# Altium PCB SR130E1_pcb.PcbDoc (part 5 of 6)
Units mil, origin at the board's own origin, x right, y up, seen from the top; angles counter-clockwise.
Board outline 5700 x 4800 mil, 6 copper layers (Top Layer, Signal Layer 1, Signal Layer 2, Signal Layer 3, Signal Layer 4, Bottom Layer), stack 61.4 mil thick; 452 components, 288 nets, 1391 pads, 911 vias.
Unrouted connection lines stored in the file: 523.
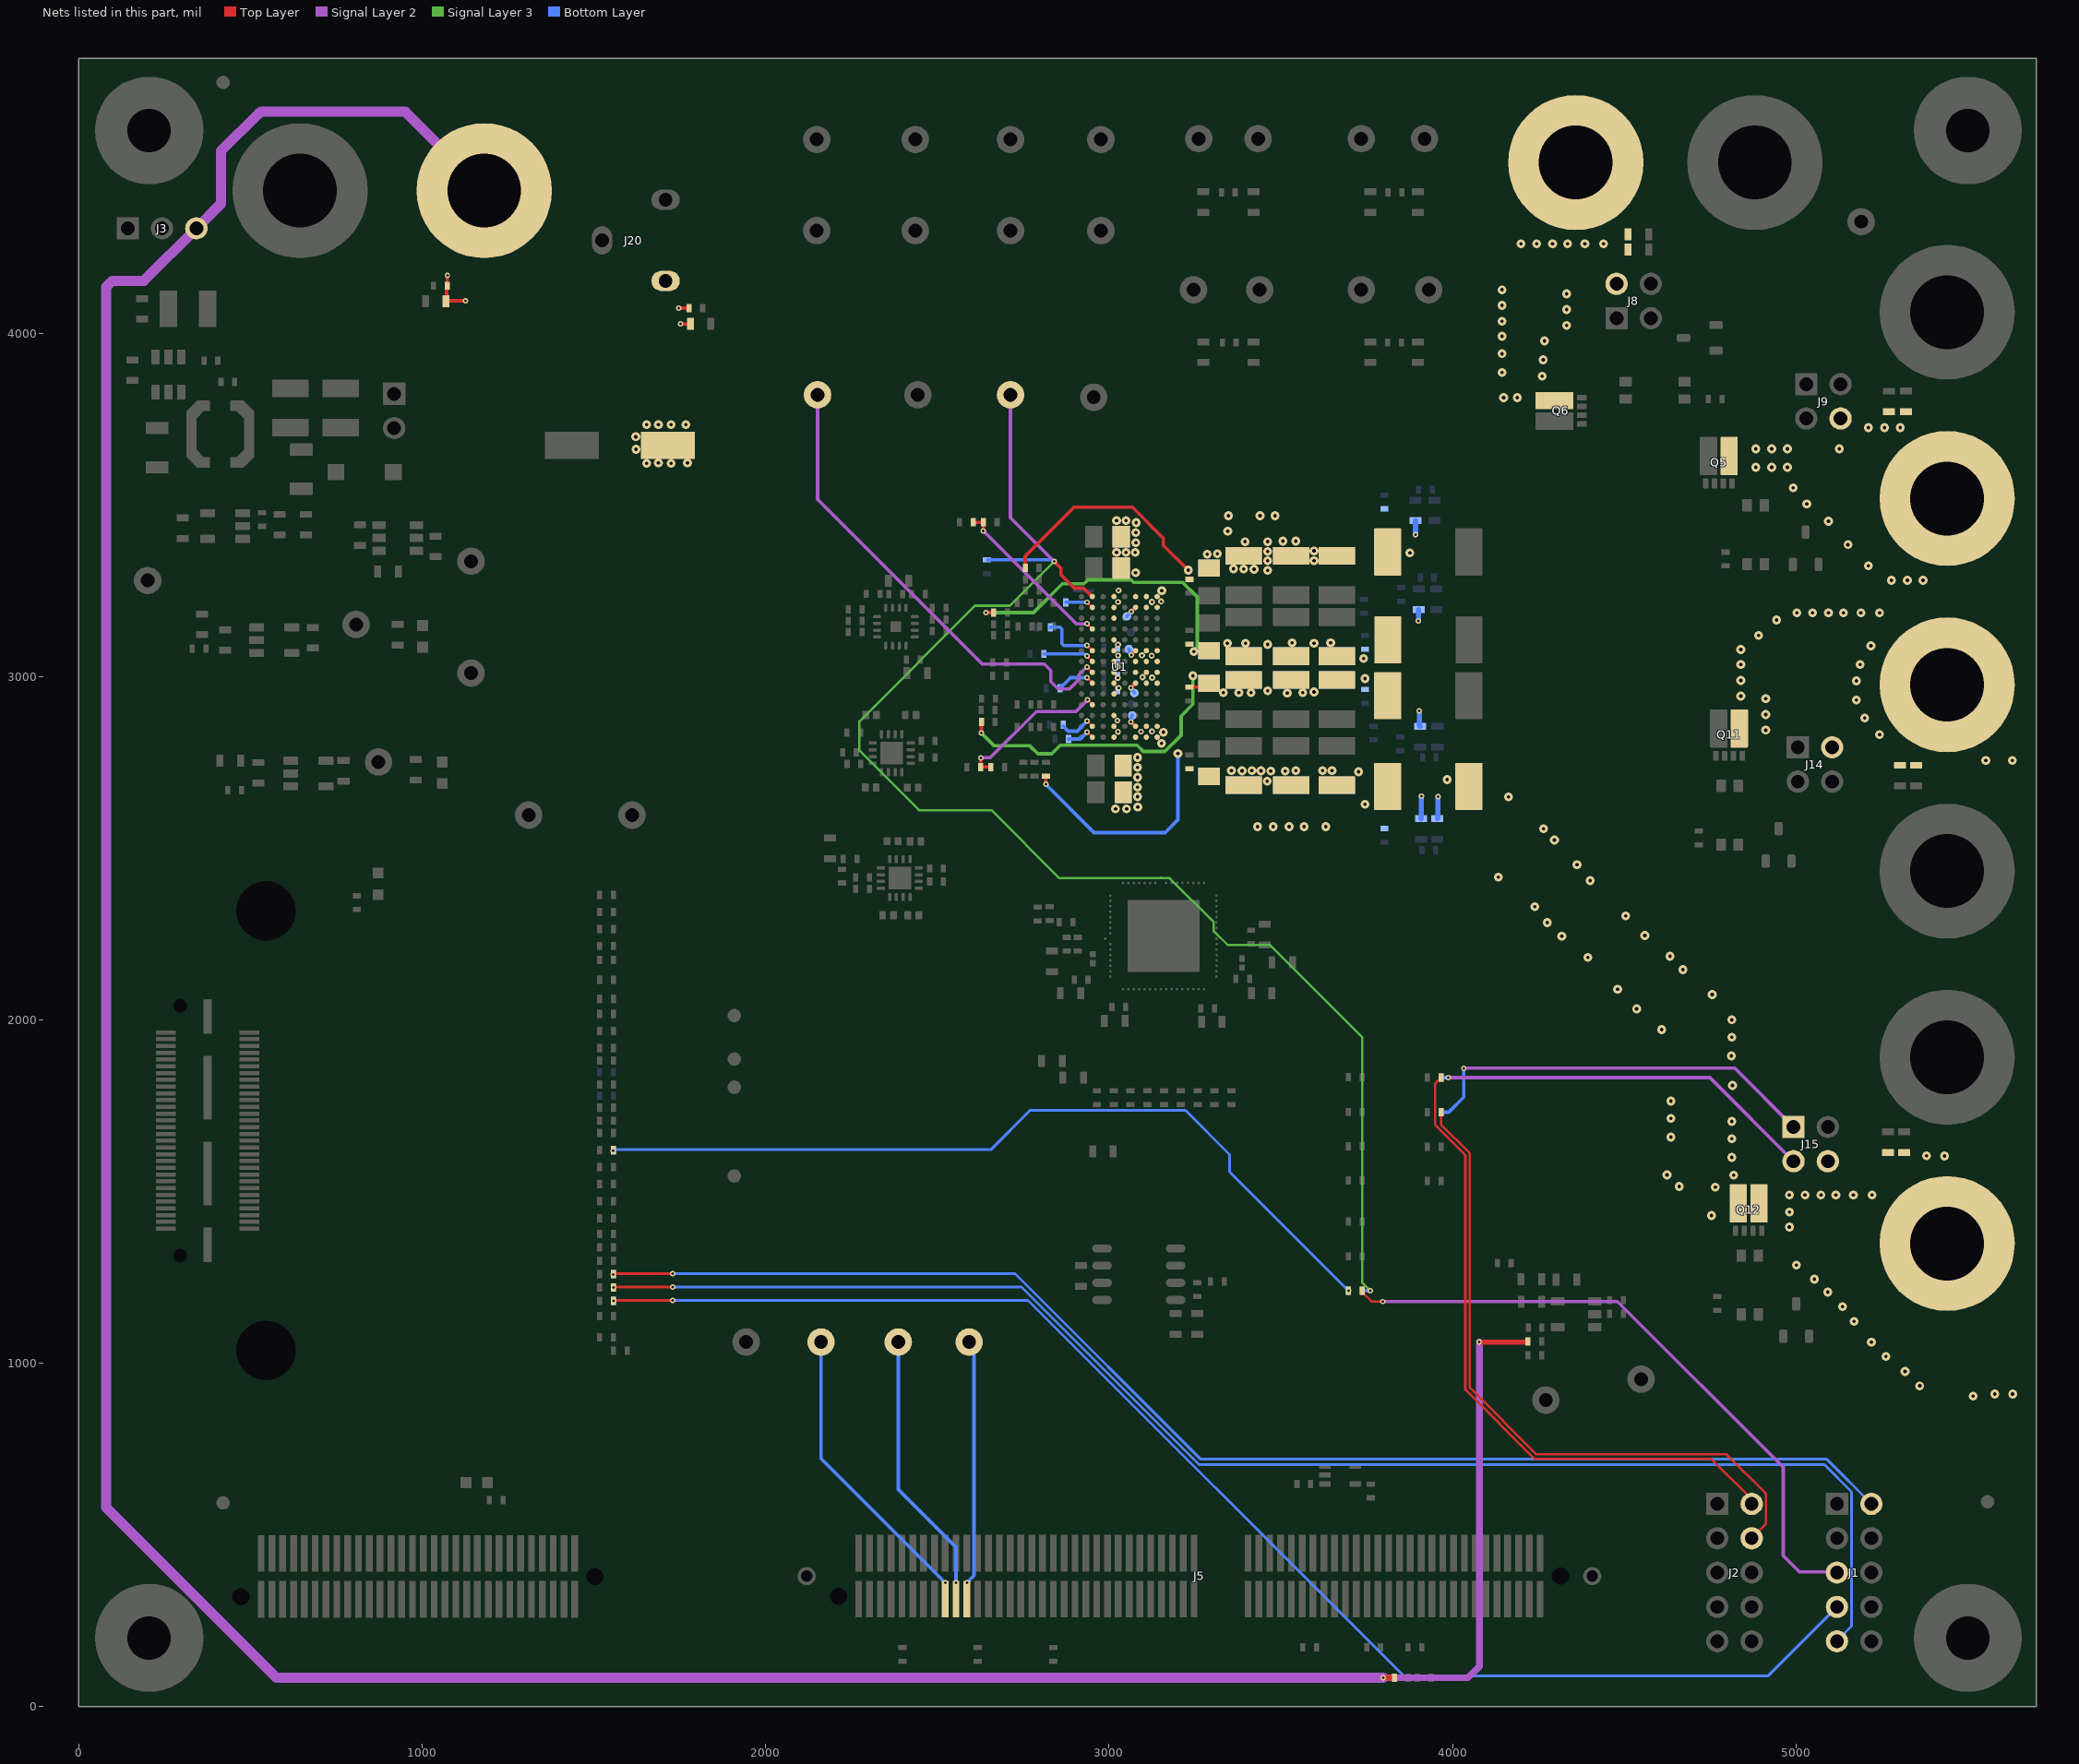
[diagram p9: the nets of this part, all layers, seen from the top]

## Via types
v1: diameter 26, hole 10, Top Layer to Bottom Layer, tented both sides, 435 vias
v2: diameter 16, hole 8, Top Layer to Bottom Layer, tented both sides, 208 vias
v3: diameter 16, hole 8, Top Layer to Bottom Layer, 145 vias
v4: diameter 16, hole 8, Top Layer to Bottom Layer, tented bottom, 46 vias
v5: diameter 19.68, hole 8, Top Layer to Bottom Layer, tented both sides, 35 vias
v6: diameter 17, hole 8, Top Layer to Bottom Layer, 30 vias
v7: diameter 18, hole 8, Top Layer to Bottom Layer, tented both sides, 6 vias
v8: diameter 16, hole 8, Top Layer to Bottom Layer, tented top, 4 vias
v9: diameter 19.68, hole 8, Top Layer to Bottom Layer, 1 vias
v10: diameter 17, hole 8, Top Layer to Bottom Layer, tented both sides, 1 vias

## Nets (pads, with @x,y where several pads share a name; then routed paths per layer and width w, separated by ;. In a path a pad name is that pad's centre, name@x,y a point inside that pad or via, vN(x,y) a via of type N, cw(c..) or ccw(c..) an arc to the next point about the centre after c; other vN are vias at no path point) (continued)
RELAY_IN4: Q12.7 Q12.8 Q12.9 R58.2 R59.2 | length 65.1
  Bottom Layer w15: R59.2@3955.74,2585.92 3957.92,2588.1 3957.92,2649.88 v2(3958.11,2650.07)
  other v1: 4754.08,1430.22 4765.43,1513 4660.38,1514.67 4818.46,1547.81 4624.58,1548.55 4813.41,1599.19 4813.41,1653.73 4636.28,1658.3 4813.41,1704.34 4636.28,1712.84 4636.28,1763.45 4815.36,1808.89 4811.85,1894.86 4813.31,1949.39 4609.31,1971.59 4813.31,2000 4536.27,2031.99 4756.28,2073.51 4480.97,2089.39 4671.31,2146.34 4394.1,2181.56 4633.04,2185.03 4318.43,2243.25 4560,2245.43 4276.13,2283.03 4504.7,2302.83 4239.62,2329.89 4401.24,2405.43 4133.92,2415.36 4362.45,2451.63 4297,2523.49 4265.41,2556.75 4163.04,2649.38 3984.3,2699.72
REMP1: C116.1 C118.1 J8.2 J11.1 Q6.5 Q6.6 Q6.10
  other v1: 4149.29,3811.78 4188.82,3811.78 4261.62,3874.74 4144.71,3885.32 4264.36,3922.12 4144.71,3939.85 4268.09,3977.43 4144.71,3990.46 4332.58,4022.26 4144.71,4033.97 4332.58,4068.75 4144.71,4080.45 4332.58,4114.37 4144.71,4126.08 4199.23,4260 4244.86,4260 4291.35,4260 4334.86,4260 4385.47,4260 4440,4260
REMP2: C117.1 C119.1 J9.4 J13.1 Q5.5 Q5.6 Q5.10
  other v1: 5277.89,3280 5324.37,3280 5370,3280 5211.25,3322.02 5151.55,3383.68 5094.89,3451.91 5031.68,3502.18 4992,3549.34 4882.95,3609.15 4929.43,3609.15 4975.06,3609.15 4882.95,3662.97 4929.43,3662.97 4975.06,3662.97 5126.48,3662.97 5211.25,3724.44 5257.73,3724.44 5303.36,3724.44
REMP3: C120.1 C122.1 J14.2 J18.1 Q11.5 Q11.6 Q11.10
  other v1: 5553,2755.51 5630,2755.51 5243.67,2830.47 4912.23,2843.64 5199.99,2878.63 4912.23,2889.27 5176.11,2931.18 4912.23,2935.76 4839.73,2942.82 5176.11,2987 4839.73,2988.45 5187,3034.45 4839.73,3034.93 4839.73,3078.44 5218.34,3088.99 4891.34,3119.31 4943.73,3164.27 5002.9,3185.51 5048.53,3185.51 5095.01,3185.51 5138.52,3185.51 5189.13,3185.51 5243.67,3185.51
REMP4: C121.1 C123.1 J15.4 J19.1 Q12.5 Q12.6 Q12.10
  other v1: 5515.91,904.52 5579.17,910 5631.12,910 5360.55,934.14 5318.07,975.81 5262.15,1020 5219.67,1061.67 5169.16,1121.63 5136.07,1164.96 5092.98,1206.87 5053.78,1244.78 5001.2,1285.38 4980.94,1396.51 4981.13,1440 4980.94,1490 5026.57,1490 5073.05,1490 5116.56,1490 5167.17,1490 5221.71,1490 5432.77,1603.34 5380.5,1604.39
REMSN4: J15.1 R62.1 | length 1199.6
  Signal Layer 2 w10: v2(4032.85,1859.04) 4821.94,1859.04 J15.1@4992.98,1688
  Bottom Layer w10: R62.1@3966.8,1730.55 3969.02,1730.55 3969.3,1730.83 3988.86,1730.83 4032.85,1774.82 v2(4032.85,1859.04)
REMSP4: J15.3 R60.1 | length 1127.1
  Signal Layer 2 w10: v2(3988.3,1831.59) 4749.39,1831.59 J15.3@4992.98,1588
  Bottom Layer w10: R60.1@3966.8,1831.59 v2(3988.3,1831.59)
RSEN4+_header: J2.2 R61.1 | length 1934.4
  Top Layer w7: R61.1@3966.8,1831.59 3966.8,1827.09 3962.8,1823.09 3958.3,1823.09 3949.8,1814.59 3949.8,1756.38 3949.8,1693.8 4037.45,1606.15 4037.45,923.05 4239.1,721.4 4754.08,721.4 4871.22,604.26 J2.2@4871.22,590.24
RSEN4-_header: J2.4 R63.1 | length 1974.3
  Top Layer w7: R63.1@3966.8,1730.55 3966.8,1695.18 4050.45,1611.54 4050.45,928.44 4244.48,734.4 4798.53,734.4 4913.2,619.73 4913.2,532.22 J2.4@4871.22,490.24
RT1: R2.2 U1.B8 | length 150
  Top Layer w7: v2(2935.75,3059.37) 2935.75,3059.28 2950.58,3044.46 U1.B8@2951.42,3044.46
  Bottom Layer w10: R2.2@2810.24,3065.69 2927.81,3065.69 2934.13,3059.37 v2(2935.75,3059.37)
RT2: R8.2 U1.B1 | length 83.6
  Top Layer w7: v2(2935.87,2838.02) 2936.17,2838.02 2950.2,2823.98 U1.B1@2951.42,2823.98
  Bottom Layer w10: R8.2@2882.26,2817.98 2916.32,2817.98 2935.87,2837.53 v2(2935.87,2838.02)
SS1: C1.1 U1.B13 | length 85
  Top Layer w7: v2(2936.09,3216.18) 2936.09,3215.9 2951.91,3200.07 U1.B13@2951.91,3199.79
  Bottom Layer w10: C1.1@2874.14,3215.96 2874.25,3216.07 2935.98,3216.07 v2(2936.09,3216.18)
SS2: C4.1 U1.B9 | length 174.8
  Top Layer w7: v2(2935.99,3090.06) 2936.19,3090.06 2950.58,3075.67 U1.B9@2951.42,3075.67
  Bottom Layer w10: C4.1@2829.57,3143.15 2830.12,3143.7 2856.81,3143.7 2862.67,3137.84 2862.67,3095.91 2868.52,3090.06 v2(2935.99,3090.06)
SS3: C9.1 U1.B6 | length 115.9
  Top Layer w7: v2(2935.76,2996.74) 2951.03,2981.46 U1.B6@2951.42,2981.46
  Bottom Layer w10: C9.1@2857.31,2965.67 2857.31,2970.17 2859.81,2972.67 2864.31,2972.67 2888.38,2996.74 v2(2935.76,2996.74)
SS4: C17.1 U1.B2 | length 109.4
  Top Layer w7: v2@2936.22,2870.96 2951.42,2855.76 U1.B2@2951.42,2855.48
  Bottom Layer w10: C17.1@2866.66,2855.19 2880.87,2840.98 2907.54,2840.98 v2(2936.45,2869.89)
SW1: pad.2@3052.27,3175.01 U1.F13 | length 31.1
  Top Layer w10: v8(3064.62,3189) 3064.62,3190.62 U1.F13@3070.95,3196.95 ; U1.F13@3076.29,3200.07 U1.F13@3077.32,3201.1
  Bottom Layer w10: pad.2@3052.27,3175.01 3052.27,3175.83 3064.62,3188.18 v8(3064.62,3189)
SW2: pad.2@3057.91,3079.86 U1.F9 | length 38.5
  Top Layer w10: v8@3064.84,3062.4 3077.32,3074.88 U1.F9@3077.32,3075.12
  Bottom Layer w10: pad.2@3057.91,3079.86 3059.82,3077.95 3059.82,3068.8 3064.84,3063.78 v8(3064.84,3062.16)
SW3: pad.2@3073.81,2951.75 U1.F6 | length 38.8
  Top Layer w10: v8@3063.65,2967.01 U1.F6@3077.32,2980.63
  Bottom Layer w10: v8(3063.61,2967.01) 3064.76,2965.86 3064.76,2963.5 3073.81,2954.45 pad.2@3073.81,2951.75
SW4: pad.2@3067.43,2886.51 U1.F2 | length 39.2
  Top Layer w10: v8(3064.07,2867.42) 3064.31,2867.42 3076.86,2854.87 3076.86,2854.64 U1.F2@3077.32,2854.64
  Bottom Layer w10: v8(3064.07,2867.42) 3064.07,2869.05 3065.52,2870.49 3065.52,2884.6 pad.2@3067.43,2886.51
SYNC_DCDC: R66.2 R67.2 R138.2 R153.1 | length 2434.8
  Top Layer w8: R153.1@1557.16,1620.6 R153.1@1558.3,1621.75
  Bottom Layer w8: R138.2@1558.3,1621.75 1730,1621.75 2655.9,1621.75 2770.24,1736.08 3222.6,1736.08 3351.16,1607.52 3351.16,1557.29 v2(3697.27,1211.18)
  other v3: 1556.18,1618.85
SYNC_DCDC_header: J1.5 R67.1 | length 1875.3
  Top Layer w7: R67.1@3737.27,1211.18 3737.27,1206.68 3764.39,1179.56 v3(3797.52,1179.56)
  Signal Layer 2 w10: v3(3797.52,1179.56) 4480.44,1179.56 4962.91,697.09 4962.91,439.39 5010.17,392.13 5059.17,392.13 J1.5@5119.67,392.13
SYNC_EX_2: J1.7 R116.1 R171.2 | length 4098.7
  Top Layer w8: R171.2@1557.16,1181.96 1558.3,1183.11 v3(1730,1183.11)
  Bottom Layer w8: v3(1730,1183.11) 2764.31,1183.11 3857.41,90 4919.43,90 J1.7@5119.67,290.24
  other v3: 1557.33,1182.13
SYNC_EX_3: J1.9 R117.1 R172.2 | length 4303.6
  Top Layer w8: R172.2@1557.16,1220.76 1558.3,1221.91 v3(1730,1221.91)
  Bottom Layer w8: v3(1730,1221.91) 2745.3,1221.91 3262.53,704.68 5083.19,704.68 5162.15,625.72 5162.15,234.61 J1.9@5119.67,192.13
  other v3: 1557.43,1220.94
SYNC_EX_4: J1.2 R118.1 R173.2 | length 3940.7
  Top Layer w8: R173.2@1557.16,1259.57 1558.3,1260.71 v3(1730,1260.71)
  Bottom Layer w8: v3(1730,1260.71) 2726.3,1260.71 3265.61,721.4 5088.5,721.4 J1.2@5219.67,590.24
  other v3: 1556.18,1258.6
SYNC_OUT: TP7.1 U1.B7 | length 1393.3
  Top Layer w7: v2(2935.57,3028.02) 2950.63,3012.96 U1.B7@2951.42,3012.96
  Signal Layer 2 w10: TP7.1@2151.38,3820.18 2151.38,3515.56 2630.99,3035.95 2811.64,3035.95 2830.25,3017.35 2830.25,2985.27 2852.09,2963.42 2884.63,2963.42 2889.21,2968 2889.41,2968 2912.67,2991.26 2912.67,3005.11 v2(2935.57,3028.02)
SYNC_powerSch: R13.2 R66.1 TP3.1 U1.B14 | length 4342.8
  Top Layer w10: v2(2840.07,3335.09) 2859.71,3315.44 2859.71,3296.55 2898.9,3257.35 2925.85,3257.35 U1.B14@2951.91,3231.29
  Signal Layer 2 w10: TP3.1@2713.15,3820.18 2713.15,3462 v2(2840.07,3335.09)
  Signal Layer 3 w7: v2(2840.07,3335.09) 2711.13,3206.15 2609.84,3206.15 2273.24,2869.55 2273.24,2784.11 2446.67,2610.67 2657.39,2610.67 2855.29,2412.78 3176.93,2412.78 3305.25,2284.46 3305.25,2257.93 3345.05,2218.14 3468.59,2218.14 3737.27,1949.46 3737.27,1234.82 v2(3760.9,1211.18)
  Bottom Layer w10: R13.2@2644.92,3339.8 2833.73,3339.8 2838.44,3335.09 v2(2840.07,3335.09) ; R66.1@3737.27,1211.18 v2(3760.9,1211.18)
TEST1: J5.100 TP35.1 | length 763.2
  Top Layer w10: J5.100@2586.1,313.07 v3(2586.1,360.5)
  Bottom Layer w10: v3(2586.1,360.5) 2607.1,381.5 2607.1,1020.81 2606.23,1021.68 2606.23,1048.27 TP35.1@2592.83,1061.66
TEST2: J5.102 TP36.1 | length 818.3
  Top Layer w10: J5.102@2554.6,313.07 v3(2554.6,360.5)
  Bottom Layer w10: TP36.1@2386.33,1061.66 2386.33,632.2 2554.6,463.93 v3(2554.6,360.5)
TEST3: J5.104 TP37.1 | length 901.3
  Top Layer w10: J5.104@2523.11,313.07 v3(2523.11,360.5)
  Bottom Layer w10: TP37.1@2159.54,1059.56 TP37.1@2161.65,1061.66 2161.65,721.96 v3(2523.11,360.5)
V_HV: C6.1 C7.1 C8.1 C10.1 C13.1 C14.1 C15.1 C16.1 C18.1 C19.1 C20.1 C21.1 C22.1 C23.1 C24.1 C124.1 C125.1 J3.3 J20.1 J21.1 R103.2 R146.2 U1.D1 U1.D2 U1.D3 U1.D5 U1.D6 U1.D7 U1.D8 U1.D9 U1.D10 U1.D12 U1.D13 U1.D14 | length 10578.4
  Top Layer w10: C6.1@1069.77,4092.17 C6.1@1071.59,4093.98 ; v3(1073.4,4167.68) C7.1@1073.4,4137.68 1071.59,4135.87 C6.1@1071.59,4093.98 ; v3(1126.37,4094.38) 1071.98,4094.38 C6.1@1071.59,4093.98 ; v3(1747.33,4072.49) C125.1@1777.01,4072.49 ; v3(1751.92,4026.56) C124.1@1780.79,4026.56
  Top Layer w15: v2(3798.03,84.04) 3830.93,84.04 R146.2@3830.93,83.63 ; v2(4078.15,1061.72) R103.2@4218.44,1061.72
  Signal Layer 2 w20: v2(3798.03,84.04) 3830.52,84.04 ; 3830.93,83.63 3830.52,84.04 ; v2(4078.15,1061.72) 4078.15,117.43 4044.76,84.04 3830.52,84.04
  Signal Layer 2 w30: J21.1@1180.94,4414.96 950.91,4645 531.22,4645 526.22,4640 524.5,4640 414.61,4530.11 414.61,4376.82 J3.3@342.74,4304.95 189.25,4151.46 97.57,4151.46 80,4133.89 80,579.37 575.33,84.04 v2(3798.03,84.04)
  other v1: 3019.03,2614.21 3051.25,2614.21 3083.92,2619.37 3083.21,2650.07 3083.21,2677.44 3083.21,2706.14 3083.21,2735.22 3083.21,2764.09 3077.28,3302.44 3022.07,3361.43 3049.6,3361.43 3076.29,3361.43 3078.13,3389.64 3078.13,3418.9 3079.1,3447.78 3022.07,3454.31 3049.6,3454.31 1653.7,3620.51 1725.26,3620.87 1688.06,3621.9 1772.63,3621.9 1622.61,3661.56 1622.33,3698.04 1653.7,3733.2 1688.06,3733.2 1768.05,3733.2 1725.26,3733.71
  other v6: 3025.99,2839.09 3024.64,2871.46 3028.11,2966.32 3025.6,2995.85 3025.88,3028.28 3026.42,3061 3026.42,3092.57 3026.42,3216.85 3027.95,3250.61
VCC1: R16.2 R17.2 U1.B11 | length 491
  Top Layer w7: v2(2936.09,3153.17) 2951.91,3137.34 U1.B11@2951.91,3136.8
  Top Layer w10: R17.2@2605.04,3448.85 R16.2@2634.09,3448.85 v2(2634.09,3424)
  Signal Layer 2 w10: v2(2634.09,3424) 2904.92,3153.17 v2(2936.09,3153.17)
VCC2: R20.2 R21.2 U1.B4 | length 459.5
  Top Layer w7: v2@2935.98,2933.95 U1.B4@2951.42,2918.51
  Top Layer w10: v2(2626.53,2763.36) 2626.35,2763.18 2626.35,2736.6 R20.2@2626.16,2736.42 R21.2@2655.74,2736.42
  Signal Layer 2 w10: v2(2626.53,2763.36) 2654.23,2763.36 2788.78,2897.9 2903.67,2897.9 v2(2937.7,2931.93)
VOUT1: C26.1 C31.1 C35.1 C39.1 C43.1 C47.1 C51.1 C56.1 C60.1 R24.1 R26.2 R31.2 R35.1 U1.F14 U1.G13 U1.G14 U1.H13 U1.H14 | length 696.6
  Top Layer w10: R26.2@2756.23,3316.25 2756.23,3350.56 2898.43,3492.76 3068.06,3492.76 3158.29,3402.53 3158.29,3381.67 v1(3230.6,3309.36)
  Bottom Layer w15: v2(3892.6,3412.62) R31.2@3892.6,3453.49
  other v1: 3153.62,3250.02 3461.78,3309 3422.52,3312.09 3391.78,3313.17 3362.35,3313.58 3462.12,3336.97 3597.07,3337.38 3285.57,3355.56 3315.67,3356.88 3876.1,3359.73 3462.12,3364.08 3597.07,3365.67 3396.35,3392.57 3462.12,3392.57 3506.05,3393.93 3543.79,3393.93 3345.52,3423.35 3347.62,3468.26 3439.73,3468.26 3483.24,3468.26
  other v7: 3124.98,3216.74 3151.96,3218.56
VOUT2: C27.1 C32.1 C36.1 C40.1 C44.1 C48.1 C52.1 C57.1 C61.1 R25.1 R29.2 R37.2 R40.1 U1.F8 U1.G8 U1.G9 U1.H8 U1.H9 | length 899.2
  Top Layer w10: v2(2641.64,3185.81) R29.2@2664.37,3185.81
  Signal Layer 2 w10: v1(3597.07,3096.49) v1@3601.4,3096.49
  Signal Layer 3 w10: v2(2641.64,3185.81) 2780.08,3185.81 2863.97,3269.7 2927.22,3269.7 2938.87,3281.35 3064.42,3281.35 3071.76,3274.02 3214.39,3274.02 3256.85,3231.55 3256.85,3086.67 3246.8,3076.62 v1(3246.8,3072.29)
  Bottom Layer w10: R37.2@3901.05,3194.18 R37.2@3901.58,3194.71
  Bottom Layer w15: v2(3901.05,3161.58) R37.2@3901.05,3194.18
  other v1: 3741.19,3051.96 3462.12,3093.06 3344.65,3096.49 3397.34,3096.72 3532.8,3098 3645.32,3098
  other v7: 3095.77,3061.27
  other v10: 3124.23,3060.33
VOUT3: C28.1 C33.1 C37.1 C41.1 C45.1 C49.1 C53.1 C58.1 C62.1 R22.1 R39.2 R54.2 R55.1 U1.F7 U1.G6 U1.G7 U1.H6 U1.H7 | length 971.7
  Top Layer w10: v2(2628.47,2835.26) R39.2@2628.47,2867.73 ; C28.1@3234.42,2968.8 3281.14,2968.8 C37.1@3291.67,2979.34
  Signal Layer 3 w10: v2(2628.47,2835.26) 2665.71,2798.01 2769.45,2798.01 2792.62,2774.84 2833.45,2774.84 2858.41,2799.8 3081.44,2799.8 3099.97,2781.27 3162.57,2781.27 3209.86,2828.56 3209.86,2884.57 3244.54,2919.25 v1(3244.54,3002)
  Bottom Layer w15: v2(3903.67,2899.34) 3903.67,2857.22 3906.17,2854.72 R54.2@3906.27,2854.72
  other v1: 3519.08,2951.75 3333.17,2952.69 3378.04,2952.69 3413.73,2952.69 3563.94,2952.69 3597.07,2954.86 3462.12,2957.97 3745.25,2993.63
  other v7: 3125.61,2996.62 3097.82,2997.59
VOUT4: C29.1 C34.1 C38.1 C42.1 C46.1 C50.1 C54.1 C59.1 C63.1 R23.1 R32.2 R56.2 R58.1 U1.F1 U1.G1 U1.G2 U1.H1 U1.H2 | length 741.7
  Top Layer w10: v2(2815.92,2685.82) R32.2@2815.92,2710.14
  Bottom Layer w10: v2(2815.92,2685.82) 2956.4,2545.34 3163.54,2545.34 3200.85,2582.65 v1(3200.85,2775.28)
  Bottom Layer w15: R56.2@3908.18,2585.92 3909.51,2587.25 v2(3909.51,2651.53)
  other v1: 3432.43,2562.67 3478.06,2562.67 3524.55,2562.67 3568.06,2562.67 3630.86,2562.67 3745.54,2627.61 3460.8,2694.83 3726.67,2722.68 3470.94,2724.31 3387.2,2725.09 3442.28,2725.09 3513.3,2724.68 3356.66,2725.66 3415.85,2725.66 3543.68,2725.66 3621.42,2726.07 3649.51,2725.66 3152.63,2805.27 3158.06,2837.74
  other v2: 3093.15,2839.37
  other v7: 3124.98,2839.73
pads on no net: FID1.1 FID2.1 FID3.1 H1.0 H2. H3.1 H4. H5.0 H6.1 H7.0 H8.1 H10.0 H11.1 J5.1 J5.2 J5.3 J5.4 J5.5 J5.6 J5.8 J5.9 J5.11 J5.12 J5.14 J5.15 J5.17 J5.18 J5.20 J5.21 J5.23 J5.24 J5.25 J5.26 J5.27 J5.31 J5.32 J5.33 J5.34 J5.36 J5.37 J5.39 J5.40 J5.41 J5.42 J5.43 J5.44 J5.45 J5.51 J5.52 J5.55 J5.56 J5.59 J5.60 J5.63 J5.64 J5.66 J5.76 J5.77 J5.78 J5.80 J5.82 J5.86 J5.88 J5.90 J5.92 J5.94 J5.106 J5.107 J5.108 J5.109 J5.110 J5.113 J5.114 J5.115 J5.116 J5.117 J5.118 J5.119 J5.120 J5.181 J5.182 J5.185 J5.186 J6.61 J6.62 J6.121 J6.122 J6.123 J6.124 J6.125 J6.126 J6.127 J6.128 J6.129 J6.130 J6.131 J6.132 J6.133 J6.134 J6.136 J6.137 J6.138 J6.139 J6.140 J6.141 J6.142 J6.143 J6.144 J6.145 J6.146 J6.147 J6.148 J6.149 J6.150 J6.151 J6.152 J6.153 J6.154 J6.155 J6.156 J6.159 J6.160 J6.161 J6.162 J6.163 J6.164 J6.165 J6.166 J6.167 J6.168 J6.169 J6.170 J6.171 J6.172 J6.173 J6.174 J6.175 J6.176 J6.177 J6.178 J7.1 J7.2 J7.4 J7.5 J7.9 J7.11 J7.13 J7.15 J7.17 J7.19 J7.21 J7.23 J7.25 J7.34 J7.36 J7.39 J7.41 J7.43 J7.45 J7.47 J7.49 J7.51 J7.53 J7.55 J7.56 J7.57 J7.58 J7.59 J7.MH1 J7.MH2 LBL1.0 SH-J1.0 SH-J2.0 SH-J3.0 SH-J4.0 SH-J5.0 SH-J6.0 SH-J7.0 SH-J8.0 SH-J9.0 SH-J10.0 U1.A1 U1.A14 U2.1 U2.3 U2.7 U2.8 U3.41 U3.42 U3.43 U3.44 U3.45 U3.46 U6.4 U9.4 U10.4 U11.1 U11.5 U12.6 U12.7 U13.6 U13.7

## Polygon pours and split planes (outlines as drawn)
PGND on Signal Layer 1 "SIGNAL_LAYER_1_PGND_P137" (solid, remove dead copper, pour order 137): 0,4800 5700,4800 5700,0 0,0
V_HV on Signal Layer 1 "SIGNAL_LAYER_1_V_HV_P136" (solid, remove dead copper, pour order 136): 932.05,4800 932.05,4261.61 1278.01,3915.65 1408.27,3915.65 1582.83,3741.09 1582.83,2905.06 1907.54,2580.35 3122.11,2580.35 3122.11,3503.11 3035.22,3590 2236.5,3590 1797.01,4029.49 1797.01,4145.06 1725.22,4216.85 1496.41,4216.85 1440,4273.26 1440,4800
RELAY_IN3 on Bottom Layer "BOTTOM_LAYER_RELAY_IN3_P149" (solid, remove dead copper, pour order 149): 3934.65,2993.63 3934.65,2892 3955.33,2871.32 4243.84,2871.32 4349.45,2765.71 4782.36,2765.71 4799.78,2783.13 4799.78,2963.45 4744.11,3019.11 3960.13,3019.11
REMP3 on Bottom Layer "BOTTOM_LAYER_REMP3_P133" (solid, remove dead copper, pour order 133): 5700,3232.6 5697.79,3232.6 4940.98,3232.6 4804.32,3095.94 4804.32,2795.65 4815.36,2784.6 4899.01,2784.6 4958.91,2844.5 4959.76,2843.64 5048.03,2843.64 5060.08,2831.6 5060.08,2746.36 5077.99,2728.45 5700,2728.45
VOUT1 on Bottom Layer "BOTTOM_LAYER_VOUT1_P106" (solid, remove dead copper, pour order 106): 3388.73,3501.03 3322.03,3501.03 3064.29,3243.29 3064.29,3226.35 3099.29,3191.35 3164.66,3191.35 3219.2,3269.34 3471.84,3269.34 3500.18,3297.67 3747.84,3297.67 3755.84,3289.67 3882.81,3289.67 3919.29,3326.15 3919.29,3459.66 3877.92,3501.03
REMP4 on Bottom Layer "BOTTOM_LAYER_REMP4_P141" (solid, remove dead copper, pour order 141): 4857.55,1419.69 4874.11,1403.13 4920.03,1403.13 4938.74,1384.43 4939.64,1290.91 5360.55,870 5700,870 5700,1638 5060.99,1638 5042.98,1619.98 5042.98,1588 4992.98,1538 4884.49,1538 4857.26,1510.77
RELAY_IN4 on Bottom Layer "BOTTOM_LAYER_RELAY_IN4_P152" (solid, remove dead copper, pour order 152): 3990.56,2750.21 3990.56,2746.2 3935.46,2691.11 3935.46,2574.97 3988.93,2521.5 4600,1910.44 4600,1541.18 4737.46,1403.72 4850.71,1403.72 4857.37,1410.37 4857.37,1999.13 4106.29,2750.21
VOUT4 on Bottom Layer "BOTTOM_LAYER_VOUT4_P134" (solid, remove dead copper, pour order 134): 3070.58,2813.49 3143.86,2740.21 3143.87,2697.97 3316.78,2525.05 3892.47,2525.05 3933.01,2565.59 3933.01,2681.95 3866.12,2748.83 3271.68,2748.83 3153.74,2866.78 3088.24,2866.78 3070.58,2849.11
VOUT3 on Bottom Layer "BOTTOM_LAYER_VOUT3_P131" (solid, remove dead copper, pour order 131): 3087.21,3022.02 3087.16,3021.96 3072.47,3021.96 3072.47,3021.94 3062.47,3011.93 3062.47,3006.47 3079.57,2989.37 3079.57,2974.01 3093.61,2959.97 3215.7,2959.59 3238.39,2936.9 3715.35,2936.9 3780.94,2871.32 3911.64,2871.32 3930.51,2890.19 3930.51,2982.92 3891.41,3022.02 3226.23,3022.02
VOUT2 on Bottom Layer "BOTTOM_LAYER_VOUT2_P109" (solid, remove dead copper, pour order 109): 3196.76,3087.69 3104.01,3087.69 3072.76,3056.44 3072.76,3042.65 3087.62,3027.78 3891.38,3027.78 3927.01,3063.41 3927.01,3175.21 3922.21,3180.01 3845.05,3180.01 3768.57,3180.01 3759.2,3170.64 3759.2,3113.62 3740.49,3110.91 3220.08,3110.91 3216.66,3107.49 3216.69,3107.62
RELAY_IN2 on Bottom Layer "BOTTOM_LAYER_RELAY_IN2_P143" (solid, remove dead copper, pour order 143): 3931.69,3059.79 3931.69,3174.68 3947.57,3185.39 4179.78,3185.64 4712.33,3718.19 4766.21,3718.19 4777.17,3707.23 4777.17,3593.27 4767.67,3583.77 4733.34,3583.77 4719.46,3569.9 4719.46,3157.37 4587.04,3024.94 3966.54,3024.94
REMP2 on Bottom Layer "BOTTOM_LAYER_REMP2_P130" (solid, remove dead copper, pour order 130): 4780.31,3708.9 4774.81,3703.4 4774.81,3586.34 4782.45,3578.7 4910.5,3578.7 5247.18,3242.02 5700,3242.02 5700,3801.11 5105.27,3801.11 5084.11,3779.95 5071.63,3708.9
REMP1 on Bottom Layer "BOTTOM_LAYER_REMP1_P108" (solid, remove dead copper, pour order 108): 4140.41,3780.55 4144.71,3776.24 4355.06,3776.5 4359.11,3780.55 4359.11,3999.25 4461.54,4101.69 4502.42,4101.69 4527.79,4127.06 4527.79,4282.24 4610,4364.45 4610,4800 4107.85,4800 4107.85,3813.11 4141.74,3779.21
RELAY_IN1 on Bottom Layer "BOTTOM_LAYER_RELAY_IN1_P142" (solid, remove dead copper, pour order 142): 3926.22,3342.88 3926.22,3464.36 3945.33,3483.47 4003.46,3541.6 4003.46,3676.69 4100.09,3773.32 4352.63,3773.32 4358.93,3767.02 4358.93,3558.93 4089.67,3289.67 3979.42,3289.67
V_HV on Bottom Layer "BOTTOM_LAYER_V_HV_P102" (solid, remove dead copper, pour order 102): 1582.83,3514.65 1622.61,3474.88 2100.09,3474.88 2151.38,3526.16 2151.38,3668.62 1797.01,4022.99 1797.01,4159.76 1782.3,4159.76 1725.22,4216.85 1496.41,4216.85 1440,4273.26 1440,4800 932.05,4800 932.05,4261.61 1278.01,3915.65 1408.27,3915.65 1582.83,3741.09
PGND on Bottom Layer "BOTTOM_LAYER_PGND_P158" (solid, remove dead copper, pour order 158): 5353.54,870 5120,1103.54 4568.63,1654.91 4568.63,1917.06 3962.2,2523.49 3962.2,2548.24 1929.46,2548.24 1582.83,2894.87 1582.83,3209.53 1158.47,3633.9 119.55,3633.9 0,3753.45 0,4800 5700,4800 5700,870
AGND on Bottom Layer "BOTTOM_LAYER_AGND_P163" (solid, remove dead copper, pour order 163): 0,4800 5700,4800 5700,0 0,0
AGND on Bottom Layer "BOTTOM_LAYER_AGND_P105" (solid, remove dead copper, pour order 105): 2919.69,3336.86 2919.69,2794.8 2618.84,2794.8 2609.49,3336.86
V_HV on Bottom Layer "BOTTOM_LAYER_V_HV_P103" (solid, remove dead copper, pour order 103): 3125.53,3507.49 3003.88,3507.49 3003.88,2553.93 3161.84,2553.93 3161.84,2713.86 3083.16,2792.55 3083.16,3275.38 3125.53,3317.76
RELAY_IN3 on Top Layer "TOP_LAYER_RELAY_IN3_P165" (solid, remove dead copper, pour order 165): 3934.65,2993.63 3934.65,2892 3955.33,2871.32 4243.84,2871.32 4349.45,2765.71 4782.36,2765.71 4799.78,2783.13 4799.78,2963.45 4744.11,3019.11 3960.13,3019.11
REMP3 on Top Layer "TOP_LAYER_REMP3_P157" (solid, remove dead copper, pour order 157): 5700,3232.6 5697.79,3232.6 4940.98,3232.6 4804.32,3095.94 4804.32,2795.65 4815.36,2784.6 4899.01,2784.6 4958.91,2844.5 4959.76,2843.64 5048.03,2843.64 5060.08,2831.6 5060.08,2746.36 5077.99,2728.45 5700,2728.45
RELAY_IN4 on Top Layer "TOP_LAYER_RELAY_IN4_P166" (solid, remove dead copper, pour order 166): 3990.56,2750.21 3990.56,2746.2 3935.46,2691.11 3935.46,2574.97 3988.93,2521.5 4600,1910.44 4600,1541.18 4737.46,1403.72 4850.71,1403.72 4857.37,1410.37 4857.37,1999.13 4106.29,2750.21
RELAY_IN2 on Top Layer "TOP_LAYER_RELAY_IN2_P164" (solid, remove dead copper, pour order 164): 3931.69,3059.79 3931.69,3174.68 3947.57,3185.39 4179.78,3185.64 4712.33,3718.19 4766.21,3718.19 4777.17,3707.23 4777.17,3593.27 4767.67,3583.77 4733.34,3583.77 4719.46,3569.9 4719.46,3157.37 4587.04,3024.94 3966.54,3024.94
RELAY_IN1 on Top Layer "TOP_LAYER_RELAY_IN1_P161" (solid, remove dead copper, pour order 161): 3926.22,3342.88 3926.22,3464.36 3945.33,3483.47 4003.46,3541.6 4003.46,3676.69 4100.09,3773.32 4352.63,3773.32 4358.93,3767.02 4358.93,3558.93 4089.67,3289.67 3979.42,3289.67
REMP4 on Top Layer "TOP_LAYER_REMP4_P160" (solid, remove dead copper, pour order 160): 4857.55,1419.69 4874.11,1403.13 4920.03,1403.13 4938.74,1384.43 4939.64,1290.91 5360.55,870 5700,870 5700,1638 5060.99,1638 5042.98,1619.98 5042.98,1588 4992.98,1538 4884.49,1538 4857.26,1510.77
VOUT4 on Top Layer "TOP_LAYER_VOUT4_P159" (solid, remove dead copper, pour order 159): 3070.58,2813.49 3143.86,2740.21 3143.87,2697.97 3316.78,2525.05 3892.47,2525.05 3933.01,2565.59 3933.01,2681.95 3866.12,2748.83 3271.68,2748.83 3153.74,2866.78 3088.24,2866.78 3070.58,2849.11
VOUT3 on Top Layer "TOP_LAYER_VOUT3_P156" (solid, remove dead copper, pour order 156): 3087.21,3022.02 3087.16,3021.96 3072.47,3021.96 3072.47,3021.94 3062.47,3011.93 3062.47,3006.47 3079.57,2989.37 3079.57,2974.01 3093.61,2959.97 3215.7,2959.59 3238.39,2936.9 3715.35,2936.9 3780.94,2871.32 3911.64,2871.32 3930.51,2890.19 3930.51,2982.92 3891.41,3022.02 3226.23,3022.02
REMP2 on Top Layer "TOP_LAYER_REMP2_P155" (solid, remove dead copper, pour order 155): 4780.31,3708.9 4774.81,3703.4 4774.81,3586.34 4782.45,3578.7 4910.5,3578.7 5247.18,3242.02 5700,3242.02 5700,3801.11 5105.27,3801.11 5084.11,3779.95 5071.63,3708.9
VOUT2 on Top Layer "TOP_LAYER_VOUT2_P154" (solid, remove dead copper, pour order 154): 3196.76,3087.69 3104.01,3087.69 3072.76,3056.44 3072.76,3042.65 3087.62,3027.78 3891.38,3027.78 3927.01,3063.41 3927.01,3175.21 3922.21,3180.01 3845.05,3180.01 3768.57,3180.01 3759.2,3170.64 3759.2,3113.62 3740.49,3110.91 3220.08,3110.91 3216.66,3107.49 3216.69,3107.62
REMP1 on Top Layer "TOP_LAYER_REMP1_P162" (solid, remove dead copper, pour order 162): 4140.41,3780.55 4144.71,3776.24 4355.06,3776.5 4359.11,3780.55 4359.11,3999.25 4461.54,4101.69 4502.42,4101.69 4527.79,4127.06 4527.79,4282.24 4610,4364.45 4610,4800 4107.85,4800 4107.85,3813.11 4141.74,3779.21
VOUT1 on Top Layer "TOP_LAYER_VOUT1_P153" (solid, remove dead copper, pour order 153): 3388.73,3501.03 3322.03,3501.03 3064.29,3243.29 3064.29,3226.35 3099.29,3191.35 3164.66,3191.35 3219.2,3269.34 3471.84,3269.34 3500.18,3297.67 3747.84,3297.67 3755.84,3289.67 3882.81,3289.67 3919.29,3326.15 3919.29,3459.66 3877.92,3501.03
V_HV on Top Layer "TOP_LAYER_V_HV_P101" (solid, remove dead copper, pour order 101): 1584.17,3513.31 1623.95,3473.54 2101.43,3473.54 2152.72,3524.82 2152.72,3667.28 1798.35,4021.65 1798.35,4158.42 1783.64,4158.42 1726.56,4215.51 1497.75,4215.51 1441.34,4271.92 1441.34,4798.66 933.39,4798.66 933.39,4260.27 1279.35,3914.31 1409.61,3914.31 1584.17,3739.75
PGND on Top Layer "TOP_LAYER_PGND_P167" (solid, remove dead copper, pour order 167): 5353.54,870 5120,1103.54 4568.63,1654.91 4568.63,1917.06 3962.2,2523.49 3962.2,2548.24 1929.46,2548.24 1582.83,2894.87 1582.83,3209.53 1158.47,3633.9 119.55,3633.9 0,3753.45 0,4800 5700,4800 5700,870
AGND on Top Layer "TOP_LAYER_AGND_P168" (solid, remove dead copper, pour order 168): 0,4800 5700,4800 5700,0 0,0
V_HV on Top Layer "TOP_LAYER_V_HV_P148" (solid, remove dead copper, pour order 148): 3004.56,2939.1 3004.56,3124.01 3033.5,3124.01 3033.5,2939.1
V_HV on Top Layer "TOP_LAYER_V_HV_P147" (solid, remove dead copper, pour order 147): 3004.38,2568.74 3004.38,2892.65 3029.64,2892.65 ccw(c3033.32,2898) 3033.33,2891.5 3033.33,2836.57 3126.27,2743.62 3126.27,2568.74
V_HV on Top Layer "TOP_LAYER_V_HV_P144" (solid, remove dead copper, pour order 144): 3113.38,3511.61 3114.25,3510.74 3114.25,3301.02 3032.2,3218.97 3032.2,3159.48 2999.17,3159.48 2994.96,3163.69 2994.96,3510.26 3003.03,3510.26 3004.38,3511.61
AGND on Top Layer "TOP_LAYER_AGND_P099" (solid, remove dead copper, pour order 99): 2151.38,3134.34 2347.06,3330.03 2759.74,3330.03 2947.72,3142.06 2947.72,2836.79 2659.16,2548.24 2304.86,2548.24 2151.38,2701.73
PGND on Signal Layer 3 "SIGNAL_LAYER_3_PGND_P150" (solid, remove dead copper, pour order 150): 5353.54,870 5120,1103.54 4568.63,1654.91 4568.63,1917.06 3962.2,2523.49 3962.2,2548.24 1929.46,2548.24 1582.83,2894.87 1582.83,3209.53 1158.47,3633.9 119.55,3633.9 0,3753.45 0,4800 5700,4800 5700,870
AGND on Signal Layer 3 "SIGNAL_LAYER_3_AGND_P151" (solid, remove dead copper, pour order 151): 0,4800 5700,4800 5700,0 0,0
AGND on Signal Layer 4 "SIGNAL_LAYER_4_AGND_P138" (solid, remove dead copper, pour order 138): 0,4800 5700,4800 5700,0 0,0
PGND on Signal Layer 2 "SIGNAL_LAYER_2_PGND_P139" (solid, remove dead copper, pour order 139): 5353.54,870 5120,1103.54 4568.63,1654.91 4568.63,1917.06 3962.2,2523.49 3962.2,2548.24 1929.46,2548.24 1582.83,2894.87 1582.83,3209.53 1158.47,3633.9 119.55,3633.9 0,3753.45 0,4800 5700,4800 5700,870
AGND on Signal Layer 2 "SIGNAL_LAYER_2_AGND_P145" (solid, remove dead copper, pour order 145): 0,4800 5700,4800 5700,0 0,0

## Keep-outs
Keep-Out Layer:
  text ".Layer_Name" at 579,-1694.49 h60

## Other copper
Top Layer:
  pour cut-out: 2773.73,3345.48 2778.73,3345.48 2778.73,3301.48 2773.73,3301.48
  pour cut-out: 2773.99,3267.35 2778.99,3267.35 2778.99,3223.35 2773.99,3223.35
  pour cut-out: 2672.83,2767.49 2677.83,2767.49 2677.83,2723.49 2672.83,2723.49
  pour cut-out: 2645.31,2932.81 2650.31,2932.81 2650.31,2888.81 2645.31,2888.81
  pour cut-out: 2749.92,2974.58 2752.55,2974.58 2754.92,2976.94 2754.92,2939 2749.92,2939
  pour cut-out: 2815.92,2983 2820.92,2983 2820.92,2897 2815.92,2897
  pour cut-out: 2815.92,3094.92 2818.11,3094.92 2820.92,3092.11 2820.92,3061 2815.92,3061
  pour cut-out: 2749.92,3105 2754.92,3105 2754.92,3066 2749.92,3061
  pour cut-out: 2815.92,3168 2820.92,3168 2820.92,3139.36 2818.11,3136.55 2815.92,3136.55
  pour cut-out: 2815.92,3236 2815.92,3192 2820.92,3192 2820.92,3231
  pour cut-out: 2775.37,3403.68 2780.37,3403.68 2780.37,3372.86 2775.37,3372.86
  pour cut-out: 2815.92,2875 2820.92,2875 2820.92,2831 2815.92,2831
  text ".Layer_Name" at 579,-1694.49 h60
Signal Layer 1:
  pour cut-out: 2577.56,3405.61 2851.84,3405.61 2855.29,3244.32 2952.16,3244.32 2952.16,2765.3 2663.91,2765.3 2663.91,3234 2577.56,3320.35
Bottom Layer:
  text ".Layer_Name" at 579,-1694.49 h60

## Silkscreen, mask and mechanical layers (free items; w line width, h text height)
Top Overlay:
  lines w10: 0,827.46 727.5,827.46 727.5,2532.46 0,2532.46 ; 40,2532.46 40,3030 295.5,3030 295.5,2532.46
  text "+ ISEN1  -" at 3204.25,4447.06 h60
  text "+ ISEN3 -" at 3690.18,4447.06 h60
  text "LSEN1+" at 2061.22,4436.39 h60
  text "LSEN2+" at 2332.98,4436.39 h60
  text "LSEN3+" at 2610.15,4436.39 h60
  text "LSEN4+" at 2888.49,4436.39 h60
  text "PGND" at 5123.48,4206.92 h60
  text "LSEN1-" at 2043.26,4177.25 h60
  text "LSEN2-" at 2351.27,4177.25 h60
  text "LSEN3-" at 2623.02,4177.25 h60
  text "LSEN4-" at 2888.49,4177.25 h60
  text "+ ISEN2 -" at 3198.91,4007.06 h60
  text "+ ISEN4 -" at 3701.92,4007.06 h60
  text "_" at 1325.85,3889.75 h60 r270
  text "+" at 1814.17,3873.38 h60 r270
  text "AGND" at 2370,3703.4 h60
  text "SYNC" at 2646.73,3702.76 h60
  text "SYNC_OUT" at 2014.14,3702.1 h60
  text "PGND" at 2889.05,3695.83 h60
  text "40 mm x 50 mm" at 2895.1,3598.24 h70
  text "--------------              -------------------------" at 4089.81,3558.14 h30 r270
  text "----------      -------     -------  --    -------  -" at 2133.25,3555.1 h30 r270
  text "-----------------------------------------------------------------" at 2149.97,3551.1 h30
  text "-5V" at 1102.07,3231.51 h60
  text "5VA" at 144.07,3156.52 h60
  text "3V3" at 765.73,3036.52 h60
  text "AGND" at 1070.21,2900.08 h60
  text "PHI COAX" at 189.33,2670 h60 r90
  text "1V8" at 826.3,2639.62 h60
  text "AGND" at 1238.16,2486.67 h60
  text "ADC_HVSS" at 1460.51,2486.01 h60
  text "PHI ON" at 969.33,2345.15 h60 r90
  text "ADC_SDOA" at 1947.29,2003.94 h60
  text "----------------------    -----------   ------------------------" at 2155.51,1943.54 h30
  text "ADC_SCLK" at 1950,1870.66 h60
  text "ADC_CSn" at 1947.29,1784.48 h60
  text "ADC_SDI" at 1947.29,1527.43 h60
  text "PHI CONTROLLER" at 706.25,1418.15 h60 r90
  text "AGND" at 1870,956.6 h60
  text "TEST3" at 2076.18,956.6 h60
  text "TEST2" at 2300.87,956.6 h60
  text "TEST1" at 2507.37,956.6 h60
  text "OPA_V-" at 4472.25,847.51 h60
  text "OPA_V+" at 4179.41,775.46 h60
  text "C2K ON" at 1048.8,721.78 h60
  text "DC431" at 3058.25,715.94 h100
  text ".Layer_Name" at 579,-1694.49 h60
Bottom Overlay:
  text ".Layer_Name" at 579,-1694.49 h60
Top Paste:
  text ".Layer_Name" at 579,-1694.49 h60
Bottom Paste:
  text ".Layer_Name" at 579,-1694.49 h60
Top Solder:
  text ".Layer_Name" at 579,-1694.49 h60
  text ".Layer_Name" at 579,-1694.49 h60
Bottom Solder:
  text ".Layer_Name" at 579,-1694.49 h60
Drill Guide:
  text ".Layer_Name" at 579,-1694.49 h60
M1 Board Outline:
  the board outline again, w10
  text ".Layer_Name" at 579,-1694.49 h60
M2 Board Dimensions:
  rectangle: 2,-1111 127,-986
  rectangle: 127,-1236 502,-1111
  lines w7: 2,-1111 1002,-1111 ; 127,-1236 127,-986 ; 252,-1236 252,-986 ; 502,-1236 502,-986 ; 752,-1236 752,-986 ; 2,-1236 1002,-1236 1002,-986 2,-986 2,-1236
  text ".Layer_Name" at 579,-1694.49 h60
M3 3D STEP Top:
  text ".Layer_Name" at 579,-1694.49 h60
M4 3D STEP Bottom:
  text ".Layer_Name" at 579,-1694.49 h60
M5 Assembly Top:
  lines w10: -290,-1766.17 6310,-1766.17 ; -290,-1562.83 6312,-1562.83 ; -290,-1359.5 -290,-1969.5 3715,-1969.5 6312,-1969.5 6312,-1359.5 -289.5,-1359.5 -289.5,-1969.5 1286,-1969.5 ; 2175,-1969.5 2175,-1359.5 ; 3442,-1562.83 3442,-1359.5 ; 4282,-1562.83 4282,-1359.5 ; 4904,-1976 4904,-1773.17
  text "COMPONENTS MARKED 'DNP' SHOULD NOT BE POPULATED." at 1155.5,-1154.5 h60
  text "All vias under the BGA package shilled be tented to keep solder from flowing into them. Filled vias are required for any in-pad-vias." at 7050,-1225.43 h30
  text "ASSEMBLY VARIANT:" at 1155,-1270 h60
  text ".VariantName" at 2191,-1270 h60
  text "PCB VIEWED FROM TOP SIDE" at -226.5,-1491.67 h60
  text "BOARD #:" at 2250,-1491.67 h60
  text ".PRJ_Number" at 2795.5,-1491.67 h60
  text "REV:" at 3640,-1491.67 h60
  text ".PCB_Rev" at 3931.5,-1491.67 h60
  text "SVN REV:" at 4478,-1491.67 h60
  text ".VersionControl_RevNumber" at 4984,-1491.67 h60
  text "TID #:" at 2250,-1695 h60
  text ".TID" at 2795.5,-1695 h60
  text "PLOT NAME =" at -226.5,-1900.34 h60
  text ".plot_File_Name" at 579,-1900.34 h60
  text "GENERATED    :" at 2252,-1900.34 h60
  text ".Print_Date" at 3121.5,-1900.34 h60
  text ".Print_Time" at 3850.5,-1900.34 h60
  text "TEXAS INSTRUMENTS" at 5115,-1900.34 h60
M6 Assembly Bottom:
  lines w10: -290.5,-1563.33 6311.5,-1563.33 ; -288.5,-1766.67 6311.5,-1766.67 ; 1117.5,-1976.5 1117.5,-1773.67 ; 1739.5,-1563.33 1739.5,-1360 ; 2579.5,-1563.33 2579.5,-1360 ; 3846.5,-1970 3846.5,-1360 ; 4735.5,-1970 6311,-1970 6311,-1360 -290.5,-1360 -290.5,-1970 2306.5,-1970 6311.5,-1970 6311.5,-1360
  text "COMPONENTS MARKED 'DNP' SHOULD NOT BE POPULATED." at 6104,-1154 h60
  text ".VariantName" at 5060,-1270 h60
  text "ASSEMBLY VARIANT:" at 6099,-1270 h60
  text ".VersionControl_RevNumber" at 1037.5,-1492.17 h60
  text "SVN REV:" at 1543.5,-1492.17 h60
  text ".PCB_Rev" at 2090,-1492.17 h60
  text "REV:" at 2381.5,-1492.17 h60
  text ".PRJ_Number" at 3226,-1492.17 h60
  text "BOARD #:" at 3771.5,-1492.17 h60
  text "PCB VIEWED FROM BOTTOM SIDE" at 6248,-1492.17 h60
  text ".TID" at 3226,-1695.5 h60
  text "TID #:" at 3771.5,-1695.5 h60
  text "TEXAS INSTRUMENTS" at 906.5,-1900.84 h60
  text ".Print_Time" at 2171,-1900.84 h60
  text ".Print_Date" at 2900,-1900.84 h60
  text "GENERATED    :" at 3769.5,-1900.84 h60
  text ".plot_File_Name" at 5442.5,-1900.84 h60
  text "PLOT NAME =" at 6248,-1900.84 h60
M9 Title Sheet:
  drawing of 57 lines, arcs and shapes, not listed
  text "1" at 741.84,7200.5 h70
  text "2" at 3237.5,7200.5 h70
  text "3" at 5726.84,7200.5 h70
  text "4" at 8233.51,7200.5 h70
  text "5" at 10732.5,7200.5 h70
  text "6" at 13237.5,7200.5 h70
  text "A" at -414.5,6057.5 h70
  text "A" at 14385.5,6057.5 h70
  text "B" at -414.5,3677.5 h70
  text "B" at 14385.5,3677.5 h70
  text "C" at -414.5,1302.5 h70
  text "C" at 14385.5,1302.5 h70
  text "PROJECT TITLE:" at 11345.5,-558.5 h45
  text ".PRJ_Title" at 11395.5,-691.83 h70
  text "DESIGNED FOR:" at 11345.5,-859.5 h45
  text ".PRJ_Customer" at 11395.5,-999.5 h70
  text "D" at -414.5,-1067.5 h70
  text "D" at 14385.5,-1067.5 h70
  text "FILE NAME:" at 11345.5,-1159.5 h45
  text ".PCB_File_Name_No_Path" at 11395.5,-1279.5 h70
  text "Texas Instruments (TI) and/or its licensors do not warrant the accuracy or completeness of this specification" at 6376,-1441.34 h45
  text "ENGINEER:" at 11345.5,-1449.5 h45
  text "LAYOUT BY:" at 12850.5,-1449.5 h45
  text "or any information contained therein. TI and/or its licensors do not warrant that this design will meet" at 6331.01,-1554 h45
  text ".PRJ_Engineer" at 11395.5,-1604.49 h70
  text ".PCB_Layout" at 12901,-1604.49 h70
  text "the specifications, will be suitable for your application or fit for any particular purpose, or will operate in" at 6331.01,-1666.67 h45
  text ".Layer_Name" at 579,-1694.49 h60
  text "ALTIUM DESIGNER VERSION:" at 12850.5,-1759.5 h45
  text "an implementation. TI and/or its licensors do not warrant that the design is production worthy. You should" at 6331.01,-1779.33 h45
  text "completely validate and test your design implementation to confirm the system functionality for your application." at 6376,-1892 h45
  text ".print_Scale" at 11395.5,-1892.83 h70
  text ".Application_BuildNumber" at 12901,-1892.83 h70
  text "1" at 741.84,-2099.5 h70
  text "2" at 3237.5,-2099.5 h70
  text "3" at 5726.84,-2099.5 h70
  text "4" at 8233.51,-2099.5 h70
  text "5" at 10732.5,-2099.5 h70
  text "6" at 13237.5,-2099.5 h70
M10 Fab Notes:
  drawing of 189 lines, arcs and shapes, not listed
  text "DESIGN INFORMATION" at 12384.02,5520.17 h60
  text "MIN. TRACK WIDTH:" at 11739.46,5388.05 h60
  text "8" at 12835.7,5388.05 h60
  text "MIL" at 12990.46,5388.05 h60
  text "7.874" at 12669.32,5266.36 h60
  text "MIN. CLEARANCE:" at 11739.46,5263.92 h60
  text "MIL" at 12990.46,5263.92 h60
  text "MIN. VIA PAD SIZE:" at 11739.46,5139.8 h60
  text "16" at 12805.71,5139.8 h60
  text "MIL" at 12990.46,5139.8 h60
  text "0.05mm (2MIL)" at 12434.46,5009.9 h60
  text "MINIMUM ANNULAR RING" at 11410.23,5001.67 h60
  text "EXTERNAL" at 13142.46,5001.67 h60
  text "PER" at 11610.23,4891.55 h60
  text "IPC-D-275 CLASS 2 LEVEL C" at 11830.23,4891.54 h60
  text "MIL, HOLES" at 13318.46,4791.07 h60
  text "+/-" at 12926,4782.48 h60
  text "+/-" at 13780,4782.48 h60
  text "REGISTRATION TOLERANCES:" at 11410.23,4781.42 h60
  text "METAL" at 12610,4781.42 h60
  text "5" at 13186.2,4781.42 h60
  text "3" at 14019.2,4781.42 h60
  text "MIL" at 14135.46,4781.42 h60
  text "HOLE SIZE TOLERANCE (UNLESS OTHERWISE SPECIFIED):" at 11410.23,4683.1 h60
  text "+/-" at 13780,4680.23 h60
  text "3" at 14019.2,4679.17 h60
  text "MIL" at 14135.46,4679.17 h60
  text "MATERIAL:" at 11335.46,4541.52 h60
  text "FR-4 High Tg" at 12321.9,4413 h60
  text "X" at 12177.46,4405.01 h60
  text "FR-4" at 11756.46,4400.49 h60
  text "OTHER" at 13244.46,4400.49 h60
  text "62 MIL (1.6mm) +/-10%" at 12076.56,4257.46 h60
  text "X" at 11956.46,4255.01 h60
  text "THICKNESS:" at 11410.23,4249.24 h60
  text "OTHER" at 13361.46,4249.24 h60
  text "TOLERANCE:" at 11410.23,4110.92 h60
  text "X" at 12258.46,4110.92 h60
  text "ANSI IPC-6012 TYPE 3 CLASS 2" at 12436.48,4110.92 h60
  text "OTHER +/-" at 12436.46,3966.73 h60
  text "BOW & TWIST:" at 11410.23,3821.54 h60
  text "X" at 12258.46,3821.54 h60
  text "ANSI IPC-6012 TYPE 3 CLASS 2" at 12436.48,3821.54 h60
  text "OTHER +/-" at 12436.46,3674.85 h60
  text "DRILLING:" at 11335.46,3544.23 h60
  text "NC_DRILL FILES" at 13096.46,3439.04 h60
  text "REFERENCE:" at 11410.23,3435.1 h60
  text "X" at 12067.46,3435.01 h60
  text "AS SHOWN" at 12245.46,3435.1 h60
  text "X" at 12968.46,3435.1 h60
  text "OTHER" at 13394.46,3292.85 h60
  text "PTH COPPER THICKNESS:" at 11409.91,3289.32 h60
  text "X" at 12549.14,3289.32 h60
  text "20-30 um" at 12677.14,3289.32 h60
  text "BOARD FINISH:" at 11335.46,3141.73 h60
  text "SILKSCREEN:" at 11490.68,3031.6 h60
  text "X" at 12448.46,3031.6 h60
  text "TOP" at 12565.46,3031.6 h60
  text "X" at 12958.46,3031.6 h60
  text "BOTTOM" at 13076.46,3031.6 h60
  text "SILKSCREEN COLOR:" at 11490.68,2876.41 h60
  text "X" at 12447.46,2876.41 h60
  text "WHITE" at 12565.46,2876.41 h60
  text "OTHER" at 13076.46,2876.41 h60
  text "X" at 12578.46,2732.96 h60
  text "GREEN" at 12696.46,2732.96 h60
  text "OTHER" at 13314.46,2732.96 h60
  text "SOLDER RESIST COLOR:" at 11490.68,2726.1 h60
  text "X" at 12578.46,2578.71 h60
  text "MATTE" at 12696.46,2578.71 h60
  text "SEMI-GLOSS" at 13314,2578.07 h60
  text "IMMERSION GOLD (ENIG)" at 12396.46,2405.94 h60
  text "ENEPIG" at 13734,2398.72 h60
  text "SURFACE FINISH:" at 11335.46,2397.72 h60
  text "X" at 12218.46,2397.72 h60
  text "IMM. TIN/SILVER OR EQUIV" at 11665,2260.4 h60
  text "OTHER" at 13096.46,2256.47 h60
  text "ARRAY/PANEL:" at 11335.46,2101.09 h60
  text "CUT AND TRIM PER M1 BOARD OUTLINE" at 12396.46,2092.87 h60
  text "N.C. ROUTE" at 12396.46,1956.9 h60
  text "X" at 13084.46,1956.9 h60
  text "V. SCORE" at 13262.46,1956.9 h60
  text "CERTIFICATION:" at 11335.46,1827.77 h60
  text "MATERIALS AND WORKMANSHIP FOR ALL PCBS" at 12060.46,1827.77 h60
  text "TO MEET OR EXCEED THE REQUIREMENTS OF:" at 12060.46,1733.71 h60
  text "X" at 11697.97,1605.08 h60
  text "ANSI IPC-A-600F CLASS ->" at 11825.96,1605.08 h60
  text "X" at 13473.97,1605.08 h60
  text "2" at 13583.96,1605.08 h60
  text "1" at 13268.96,1603.58 h60
  text "3" at 13937.96,1603.58 h60
  text "X" at 12509.97,1457.39 h60
  text "RoHS" at 12637.96,1457.39 h60
  text "OTHER" at 13282.36,1457.39 h60
  text "PER ORDER" at 13679.42,1457.39 h60
  text "ALL BOARDS MUST MEET OR EXCEED UL94-V0 REQUIREMENTS." at 11363,1303.57 h60
  text "PCB MUST BEAR THE UL94V-0 UL REGISTERED MATERIAL ID NUMBER" at 11363,1187.5 h60
  text "ADDITIONAL REQUIREMENTS:" at 11335.46,1018.08 h60
  text "MICROSECTION:" at 11410.23,910.95 h60
  text "YES" at 12315.96,910.95 h60
  text "REQUIRED" at 13177.46,766.62 h60
  text "BARE BOARD ELEC. TEST:" at 11410.23,763.76 h60
  text "NONE" at 12715.96,763.76 h60
  text "X" at 13059.46,763.76 h60
  text "PER ORDER" at 13769.46,763.76 h60
  text "XX MIL VIAS REQUIRE NON-CONDUCTIVE FILL AND PLANARIZE" at 11578.38,558.82 h59
  text "XX MIL VIAS REQUIRE CONDUCTIVE FILL AND PLANARIZE" at 11586.38,454.84 h60
  text "OUTER XX MIL TRACES REQUIRE 50 OHM SINGLE-ENDED IMPEDANCE" at 11585.39,291.46 h58
  text "LAYER 2 & 3 (INNER LAYERS) XX MIL WIDE, XX MIL SPACE / TRACES REQUIRE 100 OHM DIFFERENTIAL IMPEDANCE" at 11577.39,55.74 h60
  text ".Layer_Name" at 579,-1694.49 h60
M11 Gerber Information:
  lines w10: -290,-1766.17 6310,-1766.17 ; -290,-1562.83 6312,-1562.83 ; -290,-1359.5 -290,-1969.5 3715,-1969.5 6312,-1969.5 6312,-1359.5 -289.5,-1359.5 -289.5,-1969.5 1286,-1969.5 ; 2175,-1969.5 2175,-1359.5 ; 3442,-1562.83 3442,-1359.5 ; 4282,-1562.83 4282,-1359.5 ; 4904,-1976 4904,-1773.17
  text "ALL ARTWORK VIEWED FROM TOP SIDE" at -226.5,-1491.67 h60
  text "BOARD #:" at 2250,-1491.67 h60
  text ".PRJ_Number" at 2795.5,-1491.67 h60
  text "REV:" at 3640,-1491.67 h60
  text ".PCB_Rev" at 3931.5,-1491.67 h60
  text "SVN REV:" at 4478,-1491.67 h60
  text ".VersionControl_RevNumber" at 4984,-1491.67 h60
  text "LAYER NAME =" at -226.5,-1694.49 h60
  text "TID #:" at 2250,-1695 h60
  text ".TID" at 2795.5,-1695 h60
  text "PLOT NAME =" at -226.5,-1900.34 h60
  text ".plot_File_Name" at 579,-1900.34 h60
  text "GENERATED    :" at 2252,-1900.34 h60
  text ".Print_Date" at 3121.5,-1900.34 h60
  text ".Print_Time" at 3850.5,-1900.34 h60
  text "TEXAS INSTRUMENTS" at 5115,-1900.34 h60
M12 Stackup:
  drawing of 399 lines, arcs and shapes, not listed
  text "Layer" at 6470.09,6780 h60
  text "Name" at 6880,6780 h60
  text "Material" at 7819.74,6780 h60
  text "Thickness" at 8679.51,6780 h60
  text "Constant" at 9329.34,6780 h60
  text "Board Layer Stack" at 9899.2,6780 h60
  text "Top Overlay" at 6880,6660 h60
  text "Top Solder" at 6880,6540 h60
  text "Solder Resist" at 7819.74,6540 h60
  text "0.50mil" at 8679.51,6540 h60
  text "3.5" at 9329.34,6540 h60
  text "1" at 6470.09,6420 h60
  text "Top Layer" at 6880,6420 h60
  text "1.40mil" at 8679.51,6420 h60
  text "Dielectric 1" at 6880,6300 h60
  text "FR-4 High Tg" at 7819.74,6300 h60
  text "7.00mil" at 8679.51,6300 h60
  text "4.2" at 9329.34,6300 h60
  text "2" at 6470.09,6180 h60
  text "Signal Layer 1" at 6880,6180 h60
  text "1.40mil" at 8679.51,6180 h60
  text "Dielectric 2" at 6880,6060 h60
  text "FR-4 High Tg" at 7819.74,6060 h60
  text "14.00mil" at 8679.51,6060 h60
  text "4.2" at 9329.34,6060 h60
  text "3" at 6470.09,5940 h60
  text "Signal Layer 2" at 6880,5940 h60
  text "1.40mil" at 8679.51,5940 h60
  text "Dielectric 3" at 6880,5820 h60
  text "FR-4 High Tg" at 7819.74,5820 h60
  text "11.00mil" at 8679.51,5820 h60
  text "4.2" at 9329.34,5820 h60
  text "4" at 6470.09,5700 h60
  text "Signal Layer 3" at 6880,5700 h60
  text "1.40mil" at 8679.51,5700 h60
  text "Dielectric 4" at 6880,5580 h60
  text "FR-4 High Tg" at 7819.74,5580 h60
  text "14.00mil" at 8679.51,5580 h60
  text "4.2" at 9329.34,5580 h60
  text "5" at 6470.09,5460 h60
  text "Signal Layer 4" at 6880,5460 h60
  text "1.40mil" at 8679.51,5460 h60
  text "Dielectric 5" at 6880,5340 h60
  text "FR-4 High Tg" at 7819.74,5340 h60
  text "7.00mil" at 8679.51,5340 h60
  text "4.2" at 9329.34,5340 h60
  text "6" at 6470.09,5220 h60
  text "Bottom Layer" at 6880,5220 h60
  text "1.40mil" at 8679.51,5220 h60
  text "Bottom Solder" at 6880,5100 h60
  text "Solder Resist" at 7819.74,5100 h60
  text "0.50mil" at 8679.51,5100 h60
  text "3.5" at 9329.34,5100 h60
  text "Bottom Overlay" at 6880,4980 h60
  text ".Layer_Name" at 579,-1694.49 h60
M13 Component Bodies Top:
  text ".Layer_Name" at 579,-1694.49 h60
M14 Component Bodies Bottom:
  text ".Layer_Name" at 579,-1694.49 h60
M15 Courtyards Top:
  text ".Layer_Name" at 579,-1694.49 h60
M16 Courtyards Bottom:
  text ".Layer_Name" at 579,-1694.49 h60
